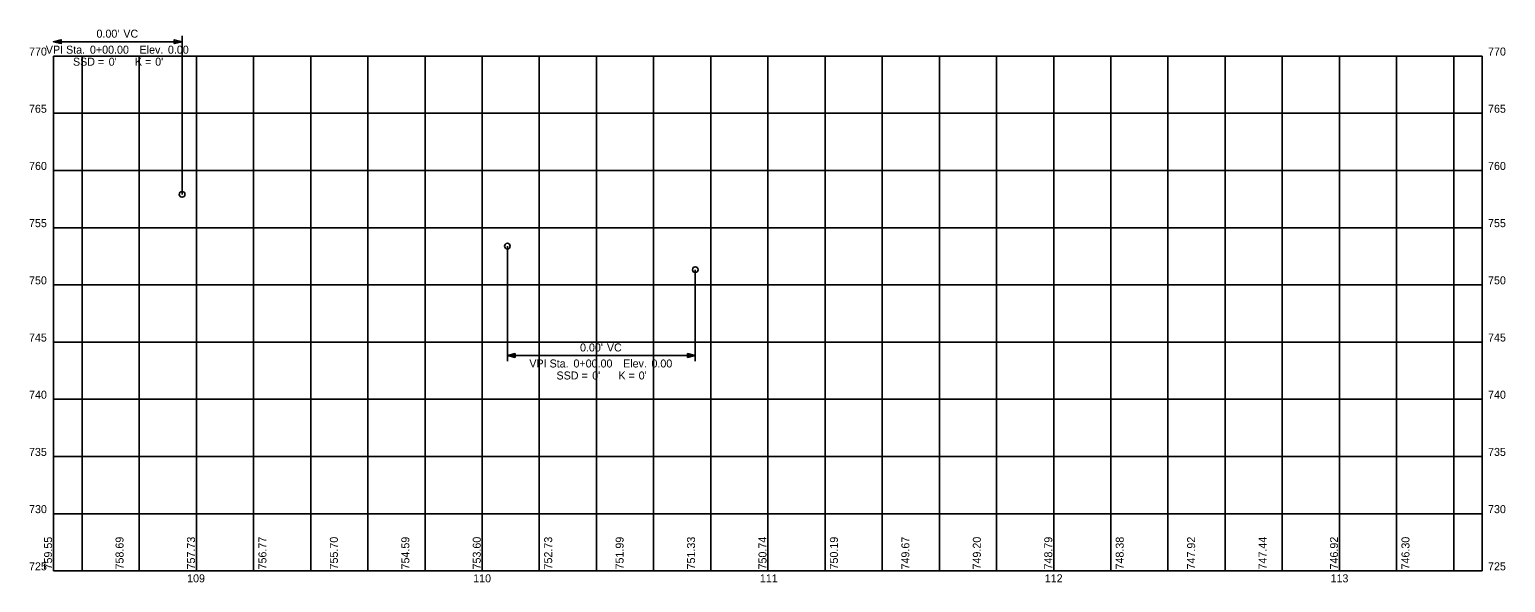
# Model space of a CAD drawing. Extents: x 529 to 1046, y 721 to 914.
import ezdxf

# ---------------------------------------------------------------- set-up
doc = ezdxf.new("R2010")
doc.units = 0
for name, color, linetype in [('PM_P_Cells', 7, 'Continuous'), ('PM_P_Crosswalk', 7, 'Continuous'), ('SC_Scratch1', 7, 'Continuous'), ('SN_X_Public', 7, 'Continuous')]:
    doc.layers.add(name, color=color, linetype=linetype)

msp = doc.modelspace()

# ---------------------------------------------------------------- linework, layer by layer
at = {"layer": 'PM_P_Crosswalk'}
for p, q in [((537.8, 910.15), (537.8, 909.95)), ((537.8, 910.05), (582.8, 910.05)), ((582.8, 856.67), (582.8, 912.05)), ((582.8, 909.95), (582.8, 910.15)), ((696.62, 838.55), (696.62, 798.33)), ((762.39, 830.33), (762.39, 798.33)), ((696.62, 800.43), (696.62, 800.23)), ((696.62, 800.33), (762.39, 800.33)), ((762.39, 800.23), (762.39, 800.43))]:
    msp.add_line(p, q, dxfattribs=at)
for points in [[(537.8, 910.05), (540.52, 910.73), (540.52, 909.37)], [(582.8, 910.05), (580.08, 909.37), (580.08, 910.73)], [(696.62, 800.33), (699.34, 801.01), (699.34, 799.65)], [(762.39, 800.33), (759.67, 799.65), (759.67, 801.01)]]:
    msp.add_lwpolyline(points, close=True, dxfattribs=at)
for centre in [(582.8, 856.67), (696.62, 838.55), (762.39, 830.33)]:
    msp.add_circle(centre, 1, dxfattribs=at)
at = {"layer": 'SC_Scratch1'}
for p, q in [((537.8, 905), (1037.8, 905)), ((537.8, 725), (537.8, 905)), ((547.8, 725), (547.8, 905)), ((567.8, 725), (567.8, 905)), ((587.8, 725), (587.8, 905)), ((607.8, 725), (607.8, 905)), ((627.8, 725), (627.8, 905)), ((647.8, 725), (647.8, 905)), ((667.8, 725), (667.8, 905)), ((687.8, 725), (687.8, 905)), ((707.8, 725), (707.8, 905)), ((727.8, 725), (727.8, 905)), ((747.8, 725), (747.8, 905)), ((767.8, 725), (767.8, 905)), ((787.8, 725), (787.8, 905)), ((807.8, 725), (807.8, 905)), ((827.8, 725), (827.8, 905)), ((847.8, 725), (847.8, 905)), ((867.8, 725), (867.8, 905)), ((887.8, 725), (887.8, 905)), ((907.8, 725), (907.8, 905)), ((927.8, 725), (927.8, 905)), ((947.8, 725), (947.8, 905)), ((967.8, 725), (967.8, 905)), ((987.8, 725), (987.8, 905)), ((1007.8, 725), (1007.8, 905)), ((1027.8, 725), (1027.8, 905)), ((1037.8, 725), (1037.8, 905)), ((537.8, 885), (1037.8, 885)), ((537.8, 865), (1037.8, 865)), ((537.8, 845), (1037.8, 845)), ((537.8, 825), (1037.8, 825)), ((537.8, 805), (1037.8, 805)), ((537.8, 785), (1037.8, 785)), ((537.8, 765), (1037.8, 765)), ((537.8, 745), (1037.8, 745)), ((537.8, 725), (1037.8, 725))]:
    msp.add_line(p, q, dxfattribs=at)

# ---------------------------------------------------------------- texts
at = {"layer": 'PM_P_Cells'}
for s, p in [('770', (529.24, 905.2)), ('770', (1039.8, 905.2)), ('765', (529.21, 885.2)), ('765', (1039.8, 885.2)), ('760', (529.24, 865.2)), ('760', (1039.8, 865.2)), ('755', (529.21, 845.2)), ('755', (1039.8, 845.2)), ('750', (529.24, 825.2)), ('750', (1039.8, 825.2)), ('745', (529.21, 805.2)), ('745', (1039.8, 805.2)), ('740', (529.24, 785.2)), ('740', (1039.8, 785.2)), ('735', (529.21, 765.2)), ('735', (1039.8, 765.2)), ('730', (529.24, 745.2)), ('730', (1039.8, 745.2)), ('725', (529.21, 725.2)), ('109', (584.55, 721)), ('110', (684.66, 721)), ('111', (784.98, 721)), ('112', (884.67, 721)), ('113', (984.68, 721)), ('725', (1039.8, 725.2))]:
    msp.add_text(s, height=2.8, dxfattribs=at).set_placement(p)
at = {"layer": 'PM_P_Crosswalk'}
for s, p in [("0.00'", (552.84, 911.45)), (' VC', (561.2, 911.45)), ('VPI Sta. ', (535.12, 905.85)), ('SSD = ', (544.61, 901.65)), ('0+00.00', (550.55, 905.85)), ("0'", (557.11, 901.65)), ('K = ', (566.3, 901.65)), ('   Elev. ', (564.79, 905.85)), ("0'", (573.37, 901.65)), ('0.00', (577.84, 905.85)), ("0.00'", (722.05, 801.73)), (' VC', (730.41, 801.73)), ('VPI Sta. ', (704.32, 796.13)), ('0+00.00', (719.76, 796.13)), ('   Elev. ', (734, 796.13)), ('0.00', (747.04, 796.13)), ('SSD = ', (713.82, 791.93)), ("0'", (726.32, 791.93)), ('K = ', (735.5, 791.93)), ("0'", (742.57, 791.93))]:
    msp.add_text(s, height=2.8, dxfattribs=at).set_placement(p)
at = {"layer": 'SN_X_Public'}
for s, p in [('759.55', (537.3, 725.5)), ('758.69', (562.31, 725.5)), ('757.73', (587.31, 725.5)), ('756.77', (612.31, 725.5)), ('755.70', (637.31, 725.5)), ('754.59', (662.31, 725.5)), ('753.60', (687.31, 725.5)), ('752.73', (712.3, 725.5)), ('751.99', (737.3, 725.5)), ('751.33', (762.3, 725.5)), ('750.74', (787.3, 725.5)), ('750.19', (812.3, 725.5)), ('749.67', (837.3, 725.5)), ('749.20', (862.3, 725.5)), ('748.79', (887.3, 725.5)), ('748.38', (912.3, 725.5)), ('747.92', (937.3, 725.5)), ('747.44', (962.3, 725.5)), ('746.92', (987.3, 725.5)), ('746.30', (1012.3, 725.5))]:
    msp.add_text(s, height=2.8, rotation=90, dxfattribs=at).set_placement(p)

doc.saveas('drawing.dxf')
